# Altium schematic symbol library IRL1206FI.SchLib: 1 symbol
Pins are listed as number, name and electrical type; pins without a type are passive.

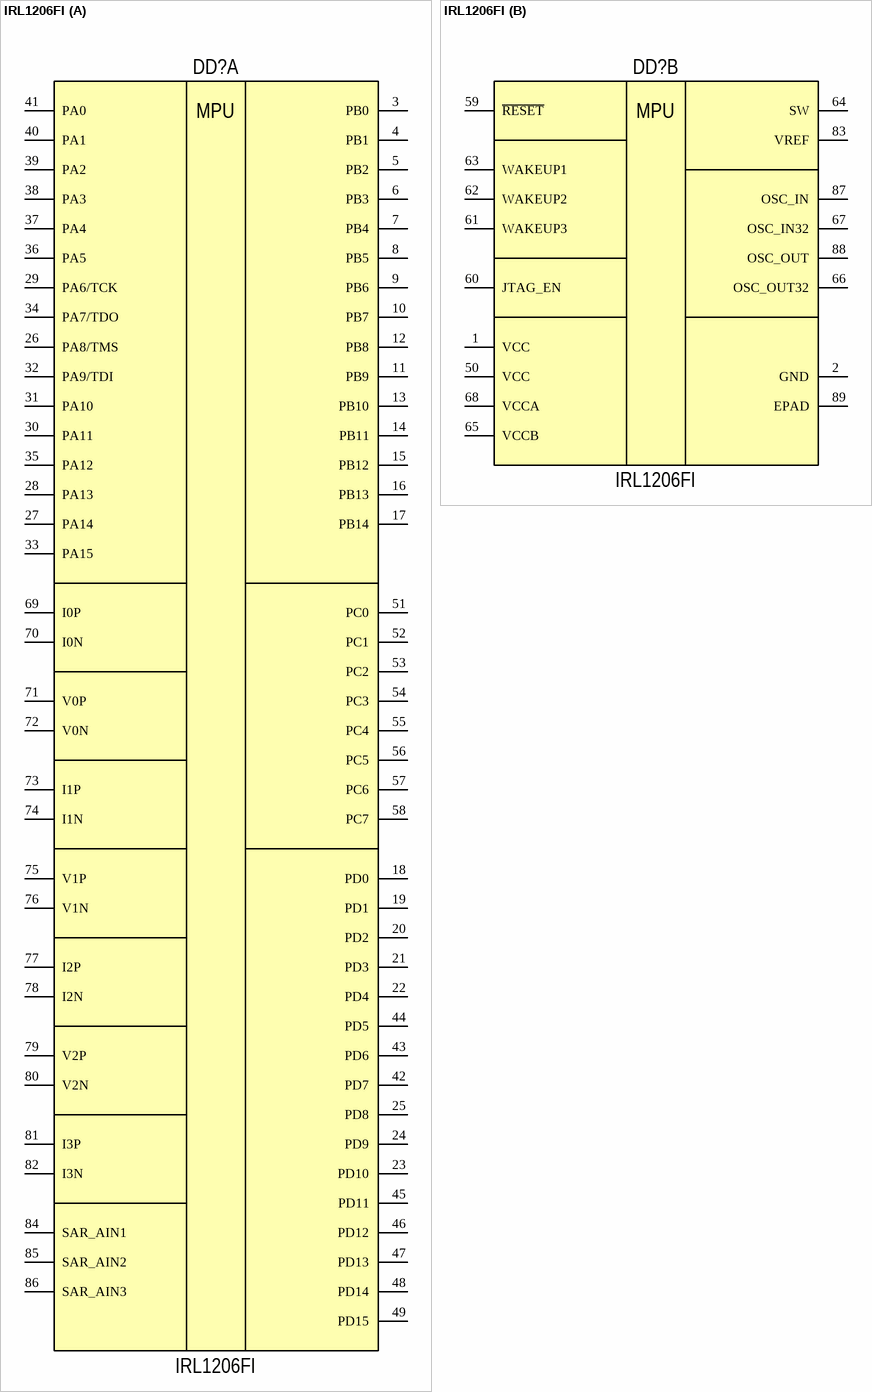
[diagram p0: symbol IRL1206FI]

## IRL1206FI
designator DD?  (value not drawn)
32-разрядный микроконтроллер на базе процессорного RISC-V ядра BM-310S0; TemperatureOperating: - 50°C to + 85°C
part A pins: 3 PB0, 4 PB1, 5 PB2, 6 PB3, 7 PB4, 8 PB5, 9 PB6, 10 PB7, 11 PB9, 12 PB8, 13 PB10, 14 PB11, 15 PB12, 16 PB13, 17 PB14, 18 PD0, 19 PD1, 20 PD2, 21 PD3, 22 PD4, 23 PD10, 24 PD9, 25 PD8, 26 PA8/TMS, 27 PA14, 28 PA13, 29 PA6/TCK, 30 PA11, 31 PA10, 32 PA9/TDI, 33 PA15, 34 PA7/TDO, 35 PA12, 36 PA5, 37 PA4, 38 PA3, 39 PA2, 40 PA1, 41 PA0, 42 PD7, 43 PD6, 44 PD5, 45 PD11, 46 PD12, 47 PD13, 48 PD14, 49 PD15, 51 PC0, 52 PC1, 53 PC2, 54 PC3, 55 PC4, 56 PC5, 57 PC6, 58 PC7, 69 I0P, 70 I0N, 71 V0P, 72 V0N, 73 I1P, 74 I1N, 75 V1P, 76 V1N, 77 I2P, 78 I2N, 79 V2P, 80 V2N, 81 I3P, 82 I3N, 84 SAR_AIN1, 85 SAR_AIN2, 86 SAR_AIN3
part B pins: 1 VCC, 2 GND, 50 VCC, 59 ~{RESET}, 60 JTAG_EN, 61 WAKEUP3, 62 WAKEUP2, 63 WAKEUP1, 64 SW, 65 VCCB, 66 OSC_OUT32, 67 OSC_IN32, 68 VCCA, 83 VREF, 87 OSC_IN, 88 OSC_OUT, 89 EPAD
